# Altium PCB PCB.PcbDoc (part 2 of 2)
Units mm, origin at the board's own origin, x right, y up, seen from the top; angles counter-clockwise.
Board outline 41 x 25.36 mm, 4 copper layers (TOP, GND, SIG, BOTTOM), stack 1.586 mm thick; 138 components, 30 nets, 293 pads, 110 vias.
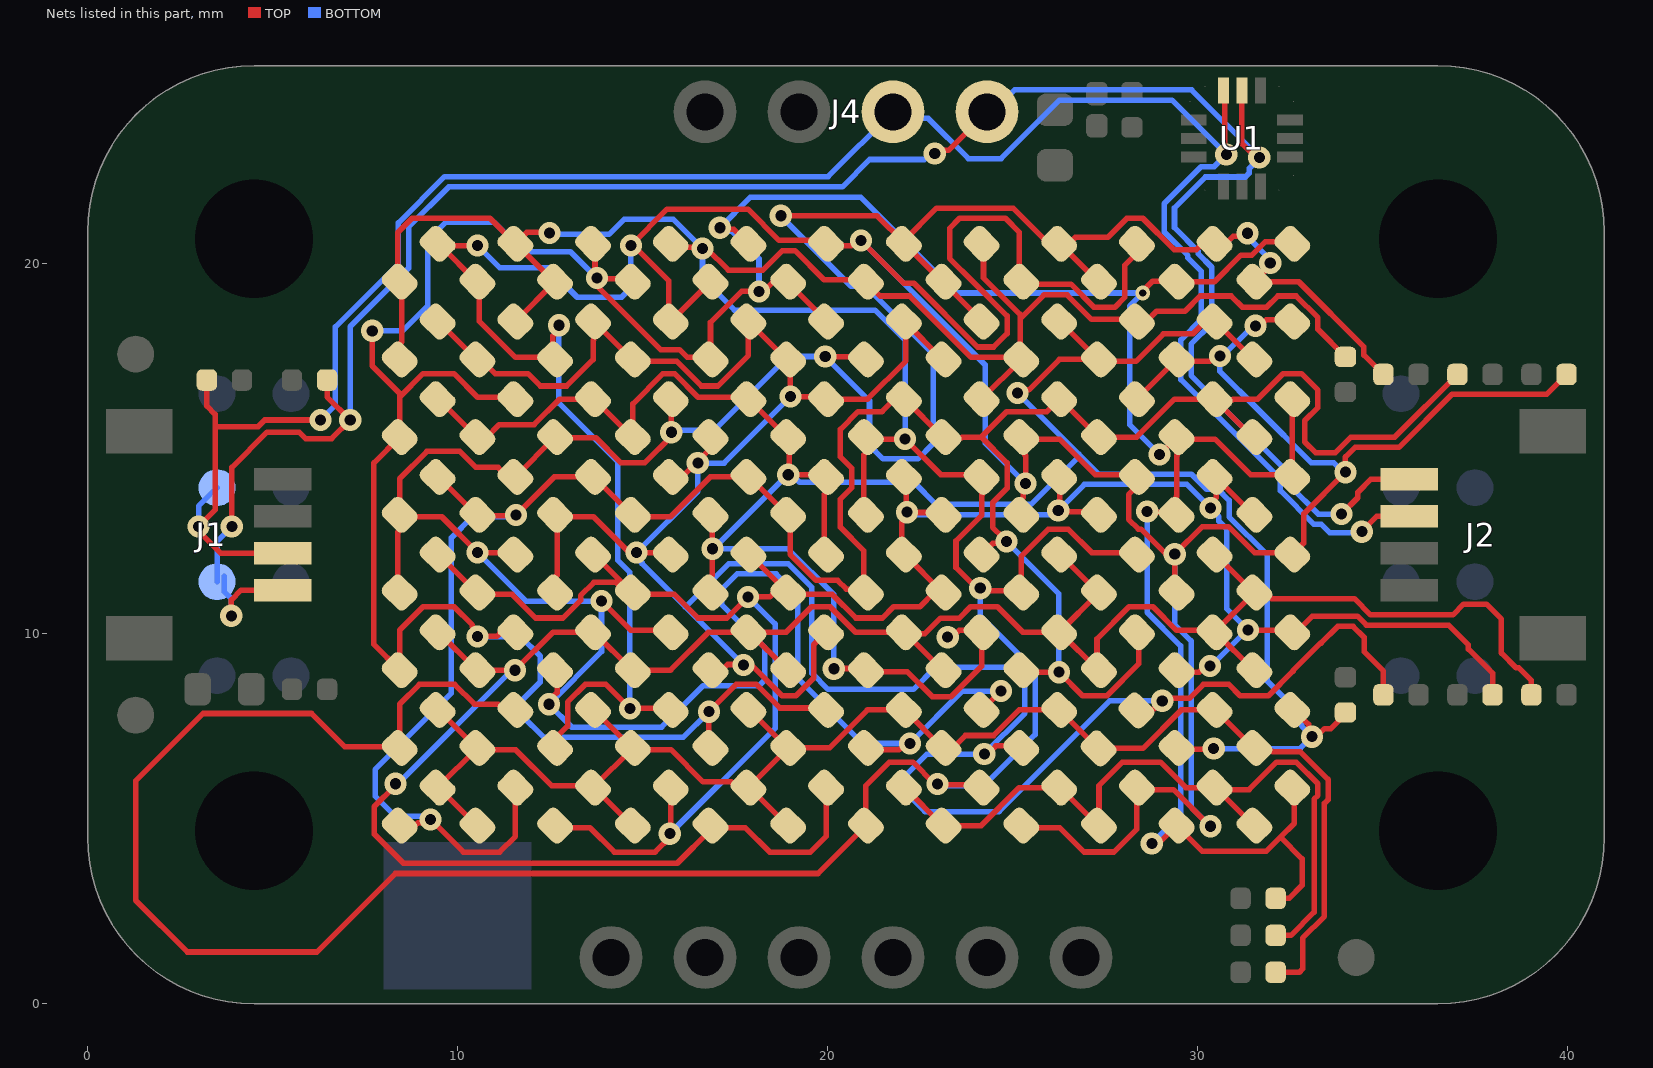
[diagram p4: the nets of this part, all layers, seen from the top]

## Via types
v1: diameter 0.6, hole 0.3, TOP to BOTTOM, tented both sides, 108 vias
v2: diameter 0.4, hole 0.2, TOP to BOTTOM, tented both sides, 2 vias

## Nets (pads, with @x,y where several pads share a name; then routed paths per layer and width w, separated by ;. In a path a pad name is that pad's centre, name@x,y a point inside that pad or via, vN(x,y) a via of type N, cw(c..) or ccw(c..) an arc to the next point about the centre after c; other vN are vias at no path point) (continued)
ROW0_3: 1.A 2.C 3.A 4.C 7.A 8.C 13.A 14.C 21.A 22.C 31.A 32.C 43.A 44.C 57.A 58.C 73.A 74.C 91.A 92.C R34.1 | length 118.3
  TOP w0.15: 13.A@8.438,17.417 8.425,17.43 8.425,17.822 8.491,17.887 8.491,19.464 1.A@8.438,19.517 8.385,19.57 8.385,20.846 8.771,21.232 10.874,21.232 2.C@11.563,20.542 ; 74.C@11.563,7.942 11.252,7.942 11.095,8.099 10.455,8.099 9.922,8.632 8.971,8.632 8.438,8.099 8.438,7.334 8.425,7.322 8.425,6.93 73.A@8.438,6.917 8.403,6.952 6.948,6.952 6.053,7.847 3.123,7.847 1.3,6.024 1.3,2.8 2.7,1.4 6.2,1.4 8.322,3.522 19.743,3.522 91.A@21.038,4.817 21.025,4.83 21.025,5.222 21.038,5.234 21.038,5.899 21.671,6.532 22.305,6.532 22.897,5.94 v1(22.97,5.94) ; 14.C@11.563,18.442 3.A@12.638,19.517 12.613,19.517 11.588,20.542 2.C@11.563,20.542 ; v1(12.486,20.833) 12.469,20.85 11.871,20.85 2.C@11.563,20.542 ; 4.C@15.763,20.542 15.852,20.454 16.588,20.454 v1(16.623,20.418) 16.731,20.418 17.32,19.83 18.252,19.83 18.781,20.358 19.122,20.358 19.91,19.57 20.985,19.57 7.A@21.038,19.517 21.423,19.132 22.218,19.132 23.88,17.47 25.185,17.47 21.A@25.204,17.451 ; 43.A@21.038,13.217 20.985,13.27 20.985,14.846 21.051,14.912 31.A@21.051,15.304 ; 31.A@21.038,15.317 31.A@21.051,15.304 ; v1@22.992,5.918 24.088,5.918 92.C@24.163,5.842 ; v1@24.08,11.185 23.474,11.792 23.474,12.51 24.163,13.2 24.163,13.742 24.176,13.755 44.C@24.176,14.229 ; v1(24.129,11.234) 24.095,11.201 24.095,11.17 25.185,11.17 57.A@25.225,11.13 ; 44.C@24.163,14.242 24.106,14.299 23.063,14.299 v1(22.098,15.264) 21.091,15.264 31.A@21.051,15.304 ; 32.C@24.163,16.342 21.A@25.238,17.417 21.A@25.204,17.451 ; 8.C@24.163,20.542 24.216,20.489 24.216,19.623 25.204,18.635 25.204,18.512 ; 57.A@25.238,11.117 57.A@25.225,11.13 ; 58.C@28.363,12.142 28.31,12.195 27.142,12.195 26.505,12.832 25.971,12.832 25.238,12.099 25.238,11.534 25.225,11.522 57.A@25.225,11.13 ; R34.1@34,17.485 33.253,18.232 33.253,18.547 32.668,19.132 32.171,19.132 31.866,18.827 31.211,18.827 30.907,19.132 30.071,19.132 29.658,18.719 28.895,18.719 28.618,18.442 22.C@28.363,18.442 28.306,18.499 27.138,18.499 26.477,19.16 25.852,19.16 25.204,18.512 ; 21.A@25.204,17.451 25.204,18.333 25.204,18.512
  BOTTOM w0.15: v1@12.484,20.83 12.52,20.795 14.095,20.795 14.504,21.204 15.833,21.204 16.621,20.416 16.621,19.612 17.481,18.751 21.281,18.751 22.096,17.937 v1@22.096,15.261 ; v1@22.967,5.938 23.008,5.897 24.236,5.897 25.613,7.274 25.613,9.011 24.126,10.498 v1@24.126,11.232
ROW1_3: 1.C 2.A 5.A 6.C 9.A 10.C 15.A 16.C 23.A 24.C 33.A 34.C 45.A 46.C 59.A 60.C 75.A 76.C 93.A 94.C R30.1 | length 113.7
  TOP w0.15: 1.C@9.463,20.542 9.511,20.494 1.C@9.536,20.494 ; v1(10.538,20.499) 10.533,20.494 1.C@9.536,20.494 ; 15.A@12.585,17.47 11.567,17.47 10.591,18.446 10.591,19.464 2.A@10.538,19.517 10.513,19.517 1.C@9.536,20.494 ; 75.A@12.638,6.917 12.638,7.171 12.974,7.507 12.974,8.153 13.452,8.632 14.01,8.632 v1(14.66,7.982) 14.667,7.989 15.717,7.989 76.C@15.763,7.942 ; 15.A@12.638,17.417 12.579,17.476 12.579,18.057 12.741,18.218 v1(12.741,18.34) ; 5.A@16.838,19.517 16.C@15.763,18.442 15.71,18.495 15.71,19.541 14.751,20.5 v1(14.685,20.5) 15.663,21.478 17.849,21.478 18.692,20.635 19.87,20.635 6.C@19.963,20.542 20.016,20.489 v1@20.643,20.489 ; v1(20.906,20.63) 22.055,19.48 22.331,19.48 24.058,17.753 24.492,17.753 24.853,18.114 24.853,18.595 23.939,19.508 23.939,19.51 23.3,20.149 23.3,20.961 23.571,21.232 24.805,21.232 25.185,20.852 25.185,19.57 9.A@25.238,19.517 25.302,19.453 26.576,19.453 27.202,18.827 27.766,18.827 28.032,19.093 28.032,19.957 28.363,20.288 10.C@28.363,20.542 ; 93.A@25.238,4.817 25.291,4.764 26.273,4.764 26.934,4.103 27.742,4.103 28.363,4.724 28.363,5.425 28.376,5.438 94.C@28.376,5.829 ; 45.A@25.238,13.217 25.225,13.23 25.225,13.622 25.292,13.688 25.292,14 v1(25.355,14.063) 25.355,14.816 25.331,14.84 25.331,15.224 33.A@25.291,15.264 ; 33.A@25.238,15.317 33.A@25.291,15.264 ; 94.C@28.363,5.842 94.C@28.376,5.829 ; 34.C@28.363,16.342 23.A@29.438,17.417 29.491,17.364 30.339,17.364 30.485,17.51 v1(30.606,17.51) ; 59.A@29.438,11.117 29.385,11.17 v1(29.385,12.152) ; v1(30.351,4.8) 30.337,4.8 29.348,5.789 28.416,5.789 94.C@28.376,5.829 ; v1(31.571,18.325) 31.693,18.325 31.863,18.495 32.51,18.495 24.C@32.563,18.442 ; R30.1@39.975,17.01 39.445,16.48 36.887,16.48 35.447,15.04 34.26,15.04 34,14.78 v1(34,14.369) 32.873,13.241 32.873,12.452 60.C@32.563,12.142 32.51,12.195 31.542,12.195 30.838,12.899 30.132,12.899 v1(29.385,12.152) ; 33.A@25.291,15.264 26.273,15.264 27.242,14.295 28.31,14.295 46.C@28.363,14.242 28.363,13.988 28.138,13.762 28.138,13.096 28.402,12.832 28.468,12.832 29.148,12.152 v1(29.385,12.152)
  BOTTOM w0.15: v1@10.536,20.497 11.136,19.897 12.436,19.897 13.236,19.097 14.436,19.097 14.682,19.343 v1@14.682,20.497 ; v1(12.741,18.34) 12.741,16.239 14.334,14.646 14.334,11.985 14.657,11.661 v1@14.657,7.979 ; v1@20.903,20.627 24.258,17.272 24.258,15.155 v1@25.352,14.061 ; v1@29.382,12.15 29.382,10.25 29.826,9.806 29.826,5.32 v1@30.349,4.797 ; v1(31.571,18.325) 31.497,18.325 30.681,17.51 v1(30.606,17.51) 30.606,17.094 31.616,16.084 33.079,14.621 33.687,14.621 33.939,14.369 v1(34,14.369)
ROW2_3: 3.C 4.A 5.C 6.A 11.A 12.C 17.A 18.C 25.A 26.C 35.A 36.C 47.A 48.C 61.A 62.C 77.A 78.C 95.A 96.C R31.1 | length 105.3
  TOP w0.15: v1(7.696,18.19) 7.696,17.241 8.438,16.499 8.438,16.399 ; 61.A@8.438,9.017 61.A@8.425,9.029 ; 62.C@11.563,10.042 11.176,10.042 11.063,9.929 v1(10.541,9.929) 10.541,10.051 10.403,10.188 10.403,10.234 9.906,10.731 9.071,10.731 8.438,10.098 8.438,9.434 8.425,9.421 61.A@8.425,9.029 ; 26.C@11.563,16.342 11.51,16.395 10.542,16.395 9.905,17.032 9.071,17.032 8.438,16.399 ; 3.C@13.663,20.542 13.716,20.489 v1@13.716,19.718 ; v1@13.716,19.615 13.716,19.458 15.49,17.684 16,17.684 16.214,17.47 16.785,17.47 17.A@16.825,17.43 ; v1@13.788,19.592 14.662,19.592 4.A@14.738,19.517 ; 77.A@16.838,6.917 16.795,6.96 v1(16.795,7.896) 17.53,8.632 18.079,8.632 18.715,7.995 19.91,7.995 78.C@19.963,7.942 ; 17.A@16.838,17.417 17.A@16.825,17.43 ; v1(17.089,20.976) 17.125,20.941 17.464,20.941 5.C@17.863,20.542 ; 18.C@19.963,18.442 19.963,18.467 18.938,19.492 6.A@18.938,19.517 18.932,19.523 18.54,19.523 18.273,19.255 v1(18.151,19.255) 17.677,19.255 16.838,18.417 16.838,17.834 16.825,17.822 17.A@16.825,17.43 ; v2(28.521,19.212) 28.521,19.261 28.79,19.53 29.425,19.53 29.451,19.504 29.842,19.504 29.855,19.517 30.456,19.517 31.177,20.238 31.471,20.238 31.829,20.595 32.51,20.595 12.C@32.563,20.542 ; v1(28.64,13.304) 28.657,13.287 29.368,13.287 47.A@29.425,13.23 ; v1@28.844,4.223 95.A@29.438,4.817 30.127,4.127 31.865,4.127 32.24,4.503 ; v1(28.971,14.85) 35.A@29.438,15.317 35.A@29.451,15.304 ; 47.A@29.438,13.217 47.A@29.425,13.23 ; R31.1@32.115,2.85 32.474,2.85 32.829,3.204 32.829,3.915 32.24,4.503 ; 96.C@32.563,5.842 32.616,5.789 32.616,4.879 32.24,4.503 ; 36.C@32.563,16.342 32.563,14.348 32.51,14.295 31.442,14.295 30.473,15.264 29.491,15.264 35.A@29.451,15.304 ; 61.A@8.425,9.029 7.738,9.716 7.738,14.617 25.A@8.438,15.317 8.425,15.33 8.425,15.722 8.438,15.734 8.438,16.399 ; 47.A@29.425,13.23 29.425,13.705 29.438,13.717 29.438,14.816 29.451,14.829 35.A@29.451,15.304
  BOTTOM w0.15: v1(7.696,18.19) 8.51,18.19 9.2,18.88 9.2,20.642 9.685,21.127 10.982,21.127 11.781,20.328 13.048,20.328 v1@13.764,19.612 ; v1@10.538,9.926 11.706,9.926 12.236,9.397 12.236,8.697 11.736,8.197 11.736,7.797 12.332,7.2 16.099,7.2 v1@16.792,7.894 ; v1@17.087,20.974 17.173,20.888 17.405,20.888 18.149,20.143 v1@18.149,19.253 ; v1(17.089,20.976) 17.916,21.803 20.897,21.803 23.488,19.212 v2(28.521,19.212) 28.517,19.212 28.165,18.86 28.165,15.656 v1(28.971,14.85) ; v1@28.636,4.206 29.547,5.117 29.547,7.98 29.549,7.982 29.549,8.398 29.547,8.4 29.547,9.673 28.636,10.583 v1@28.636,13.3
  other v1: 28.766,4.336 13.766,19.615
ROW3_3: 7.C 8.A 9.C 10.A 11.C 12.A 19.A 20.C 27.A 28.C 37.A 38.C 49.A 50.C 63.A 64.C 79.A 80.C R4.1 | length 94.6
  TOP w0.15: 49.A@8.438,11.117 8.385,11.17 8.385,12.746 8.451,12.812 37.A@8.451,13.204 ; 50.C@11.563,12.142 11.51,12.195 10.542,12.195 v1(10.538,12.199) 9.573,13.164 8.491,13.164 37.A@8.451,13.204 ; v1(12.472,8.098) 12.472,8.189 12.691,8.409 12.691,8.964 63.A@12.638,9.017 ; v1(13.893,10.887) 14.685,10.095 15.71,10.095 64.C@15.763,10.042 ; 28.C@15.763,16.342 15.779,16.326 15.779,15.34 15.066,14.627 14.41,14.627 13.738,15.299 12.656,15.299 27.A@12.638,15.317 38.C@11.563,14.242 11.356,14.242 11.099,14.499 10.495,14.499 10.063,14.932 9.171,14.932 8.438,14.199 8.438,13.634 8.425,13.622 8.425,13.23 37.A@8.438,13.217 37.A@8.451,13.204 ; v1(18.738,21.299) 21.338,21.299 7.C@22.063,20.574 ; v1(19.938,17.499) 19.953,17.485 20.97,17.485 19.A@21.038,17.417 ; 79.A@21.038,6.917 21.091,6.864 21.931,6.864 22.105,7.038 v1(22.227,7.038) ; 80.C@24.163,7.942 24.181,7.942 v1(24.69,8.451) ; 20.C@24.163,18.442 24.163,18.467 23.138,19.492 23.113,19.492 23.113,19.517 22.088,20.542 7.C@22.063,20.542 7.C@22.063,20.574 ; 9.C@26.341,20.489 27.313,19.517 10.A@27.338,19.517 ; 11.C@30.463,20.542 30.125,20.542 29.969,20.386 29.367,20.386 28.521,21.232 28.093,21.232 27.58,20.719 26.702,20.719 26.526,20.542 26.341,20.542 25.986,20.542 25.02,21.509 22.948,21.509 22.063,20.624 7.C@22.063,20.574 ; 11.C@30.823,20.548 30.823,20.6 30.965,20.742 31.265,20.742 v1(31.351,20.828) ; 12.A@31.591,19.464 12.A@31.538,19.517 ; v1(31.966,20.022) 31.866,19.922 31.866,19.845 12.A@31.538,19.517 ; R4.1@35.025,17.01 34.5,17.535 34.5,17.754 32.737,19.517 12.A@31.538,19.517
  BOTTOM w0.15: v1@10.536,12.197 11.848,10.884 13.891,10.884 13.891,9.517 12.469,8.095 13.087,7.477 15.516,7.477 16.636,8.597 18.148,8.597 18.305,8.753 18.305,9.628 17.136,10.797 17.136,11.197 17.559,11.62 18.613,11.62 19.197,11.035 19.197,8.79 20.951,7.035 22.225,7.035 23.638,8.449 v1@24.688,8.449 ; v1@15.776,15.445 15.828,15.497 16.936,15.497 18.936,17.497 19.936,17.497 21.136,16.297 21.136,15.097 21.505,14.728 22.445,14.728 22.858,15.142 22.858,17.57 21.038,19.39 20.642,19.39 v1@18.736,21.297 ; v1(31.351,20.828) 31.351,20.732 31.966,20.118 v1(31.966,20.022)
  other v1: 15.779,15.447
ROW4_3: 13.C 14.A 15.C 16.A 17.C 18.A 19.C 20.A 29.A 30.C 39.A 40.C 51.A 52.C 65.A 66.C 81.A 82.C R27.1 | length 80.6
  TOP w0.15: 13.C@9.463,18.442 9.488,18.442 10.513,17.417 10.629,17.417 11.014,17.032 11.905,17.032 12.238,16.699 12.949,16.699 13.663,17.413 13.663,17.942 13.676,17.955 15.C@13.676,18.429 ; 51.A@12.638,11.117 12.625,11.13 12.625,11.522 12.691,11.587 39.A@12.691,13.164 ; 39.A@12.638,13.217 39.A@12.691,13.164 ; 15.C@13.688,18.442 14.713,17.417 16.A@14.738,17.417 14.793,17.362 15.93,17.362 16.593,16.699 17.038,16.699 17.863,17.524 17.863,18.025 17.876,18.038 17.C@17.876,18.429 ; 52.C@15.763,12.142 15.71,12.195 v1(14.838,12.195) 14.642,12.195 13.673,13.164 39.A@12.691,13.164 ; 40.C@15.763,14.242 16.07,14.242 16.46,14.633 v1@16.512,14.633 ; v1(16.495,14.616) 16.495,14.668 16.838,15.011 29.A@16.838,15.317 ; 65.A@16.838,9.017 17.145,9.017 17.299,9.171 v1@17.733,9.171 ; 17.C@17.863,18.442 17.C@17.876,18.429 ; v1@17.932,9.171 18.775,8.327 19.149,8.327 19.627,8.806 19.627,9.707 66.C@19.963,10.042 ; 18.A@18.913,17.392 17.C@17.876,18.429 ; 18.A@18.938,17.417 18.996,17.358 18.996,16.417 v1(19.002,16.412) 19.01,16.403 19.902,16.403 30.C@19.963,16.342 19.976,16.329 20.368,16.329 20.381,16.342 21.081,16.342 22.116,17.377 22.116,18.389 19.C@22.063,18.442 22.088,18.442 23.113,17.417 20.A@23.138,17.417 ; v1(24.238,6.751) 24.33,6.751 24.549,6.97 25.185,6.97 81.A@25.238,6.917 ; 82.C@28.351,7.93 28.404,7.877 28.715,7.877 28.814,7.975 28.833,7.975 v1(29.047,8.19) 29.112,8.254 29.782,8.254 30.159,8.632 30.848,8.632 31.153,8.327 31.917,8.327 32.583,8.993 32.583,9.011 33.323,9.75 33.34,9.75 33.792,10.202 34.208,10.202 34.502,9.908 34.502,9.518 35.025,8.994 R27.1@35.025,8.35
  BOTTOM w0.15: 16.162,10.723 v1@17.731,9.153 ; v1@18.999,16.409 17.204,14.614 16.493,14.614 16.493,13.85 14.836,12.193 14.836,12.071 14.987,11.92 14.987,11.901 16.164,10.725 17.336,11.897 18.936,11.897 19.575,11.257 19.575,8.936 20.015,8.497 22.32,8.497 22.92,9.097 25.136,9.097 25.336,8.897 25.336,7.848 24.236,6.748 22.687,6.748 22.136,6.197 22.136,5.697 22.636,5.197 24.636,5.197 27.627,8.187 v1@29.045,8.187
  other v1: 17.733,9.156
ROW5_3: 21.C 22.A 23.C 24.A 25.C 26.A 27.C 28.A 29.C 30.A 41.A 42.C 53.A 54.C 67.A 68.C 83.A 84.C R33.1 | length 72.5
  TOP w0.15: 25.C@9.463,16.342 9.488,16.342 10.513,15.317 26.A@10.538,15.317 10.792,15.317 11.128,15.653 12.073,15.653 12.762,16.342 27.C@13.663,16.342 13.688,16.342 28.A@14.713,15.317 ; 28.A@14.725,15.33 14.725,15.722 14.738,15.734 14.738,16.218 15.552,17.032 15.868,17.032 16.505,16.395 17.81,16.395 29.C@17.863,16.342 30.A@18.913,15.292 ; 53.A@16.838,11.117 16.825,11.13 16.825,11.522 16.891,11.587 v1(16.891,12.299) 16.891,13.164 41.A@16.838,13.217 ; 30.A@18.938,15.317 18.965,15.29 18.965,14.325 v1(18.938,14.299) 18.94,14.297 19.908,14.297 42.C@19.963,14.242 ; 54.C@19.963,12.142 19.91,12.195 19.91,13.772 19.976,13.838 42.C@19.976,14.229 ; v1(20.17,9.056) 20.177,9.063 20.992,9.063 67.A@21.038,9.017 21.084,8.971 22.161,8.971 22.833,8.299 23.338,8.299 24.163,9.124 24.163,9.625 24.176,9.638 24.176,10.029 68.C@24.163,10.042 24.11,10.095 23.556,10.095 23.37,9.909 v1(23.248,9.909) ; v1(25.138,16.509) 25.224,16.595 25.446,16.595 26.268,17.417 26.92,17.417 26.933,17.43 22.A@27.3,17.43 ; 21.C@26.263,18.442 26.288,18.442 22.A@27.3,17.43 ; 83.A@29.438,6.917 29.473,6.881 30.421,6.881 v1(30.438,6.899) ; 24.A@31.591,17.364 24.A@31.538,17.417 31.513,17.417 30.488,18.442 23.C@30.463,18.442 30.209,18.442 29.873,18.107 29.077,18.107 28.335,17.364 27.391,17.364 22.A@27.338,17.417 27.325,17.43 22.A@27.3,17.43 ; 84.C@32.563,7.942 32.615,7.942 33.006,7.551 33.006,7.306 v1(33.092,7.22) 33.214,7.22 33.434,7.439 33.604,7.439 R33.1@34.04,7.875
  BOTTOM w0.15: v1@20.168,9.053 20.168,11.064 18.936,12.297 16.912,12.297 18.912,14.297 19.049,14.297 19.249,14.097 22.336,14.097 22.936,13.497 25.498,13.497 26.8,14.799 26.8,14.847 ; v1(25.138,16.509) 26.8,14.847 ; v1(30.438,6.899) 32.772,6.899 v1(33.092,7.22) 33.092,7.234 32.817,7.51 32.817,7.793 31.89,8.719 31.89,12.128 30.855,13.163 30.855,13.609 30.561,13.903 30.248,13.903 29.832,14.318 27.328,14.318 26.8,14.847
ROW6_3: 31.C 32.A 33.C 34.A 35.C 36.A 37.C 38.A 39.C 40.A 41.C 42.A 55.A 56.C 69.A 70.C 85.A 86.C R32.1 | length 73.5
  TOP w0.15: 85.A@8.438,4.817 8.451,4.804 8.842,4.804 8.932,4.894 9.183,4.894 v1@9.269,4.98 ; v1@9.278,4.98 10.159,4.099 11.138,4.099 11.563,4.524 11.563,5.425 11.576,5.438 11.576,5.829 86.C@11.563,5.842 ; 37.C@9.463,14.242 9.488,14.242 10.513,13.217 38.A@10.538,13.217 10.565,13.189 v1@11.553,13.189 ; v1@11.587,13.215 12.614,14.242 13.246,14.242 13.259,14.255 13.65,14.255 39.C@13.663,14.242 13.688,14.242 14.713,13.217 40.A@14.738,13.217 14.791,13.164 15.753,13.164 16.831,14.242 17.446,14.242 17.459,14.255 17.85,14.255 41.C@17.863,14.242 17.888,14.242 18.913,13.217 42.A@18.938,13.217 18.991,13.164 18.991,12.146 19.695,11.443 20.275,11.443 20.508,11.21 20.945,11.21 55.A@20.985,11.17 ; 55.A@21.038,11.117 55.A@20.985,11.17 ; 56.C@24.163,12.397 56.C@24.163,12.142 24.47,12.449 24.788,12.449 v1(24.838,12.499) ; v1@24.738,12.599 24.461,12.876 24.461,13.543 24.853,13.935 24.853,14.62 24.156,15.317 ; 69.A@25.238,9.017 25.291,8.964 v1(26.257,8.964) 26.894,8.327 27.549,8.327 28.416,9.194 28.416,9.989 70.C@28.363,10.042 ; 35.C@30.463,16.342 35.C@30.476,16.329 ; 35.C@30.463,16.355 30.059,16.355 30.046,16.342 29.381,16.342 28.356,15.317 27.755,15.317 27.742,15.304 27.351,15.304 34.A@27.338,15.317 27.313,15.317 26.288,16.342 33.C@26.263,16.342 25.927,16.007 24.846,16.007 24.156,15.317 ; 36.A@31.538,15.317 31.488,15.317 35.C@30.476,16.329 ; R32.1@37.025,17.01 35.332,15.317 34.145,15.317 33.726,14.898 33.192,14.898 32.898,15.192 32.898,15.759 33.253,16.114 33.253,16.589 32.81,17.032 32.318,17.032 31.628,16.342 30.964,16.342 30.951,16.329 35.C@30.476,16.329 ; 55.A@20.985,11.17 20.985,12.244 20.348,12.88 20.348,13.643 20.653,13.947 20.653,14.478 20.348,14.783 20.348,15.528 20.827,16.007 21.473,16.007 21.809,16.342 31.C@22.063,16.342 22.088,16.342 23.113,15.317 32.A@23.138,15.317 23.151,15.304 23.625,15.304 23.638,15.317 24.156,15.317
  BOTTOM w0.15: v1(9.27,4.98) 9.183,5.066 8.965,5.066 8.957,5.075 8.31,5.075 7.771,5.614 7.771,6.332 9.836,8.397 9.836,12.597 10.407,13.168 11.531,13.168 v1@11.576,13.213 ; v1@24.836,12.497 26.255,11.077 v1@26.255,8.961
  other v1: 11.579,13.215
ROW7_3: 43.C 44.A 45.C 46.A 47.C 48.A 49.C 50.A 51.C 52.A 53.C 54.A 55.C 56.A 71.A 72.C 87.A 88.C R28.1 | length 64
  TOP w0.15: 49.C@9.463,12.142 9.488,12.142 10.513,11.117 50.A@10.538,11.117 10.591,11.064 11.473,11.064 12.11,10.427 12.849,10.427 13.327,10.906 13.327,11.031 13.685,11.389 14.288,11.389 14.56,11.117 52.A@14.738,11.117 14.791,11.064 15.862,11.064 16.499,10.427 17.282,10.427 v1(17.853,10.999) 18.441,10.999 18.558,11.117 54.A@18.913,11.117 ; 87.A@12.638,4.817 12.691,4.764 13.573,4.764 14.238,4.099 15.338,4.099 v1@15.763,4.524 ; 51.C@13.663,12.142 13.688,12.142 52.A@14.7,11.13 ; v1@15.763,4.599 15.763,5.425 15.776,5.438 15.776,5.829 88.C@15.763,5.842 ; 53.C@17.863,12.142 17.888,12.142 54.A@18.913,11.117 ; 43.C@22.063,14.242 22.133,14.173 22.133,13.305 v1(22.149,13.288) ; 56.A@23.138,11.117 56.A@23.113,11.117 ; 44.A@23.138,13.217 23.076,13.279 22.158,13.279 v1(22.149,13.288) ; 45.C@26.263,14.242 26.277,14.228 26.277,13.373 v1(26.238,13.334) 26.27,13.302 27.253,13.302 46.A@27.338,13.217 ; 71.A@29.438,9.017 29.491,8.964 30.046,8.964 30.216,9.134 v1(30.338,9.134) ; v1(30.353,13.401) 30.353,13.523 30.51,13.68 30.51,14.161 30.527,14.178 47.C@30.463,14.242 ; 47.C@30.54,14.191 31.513,13.217 48.A@31.538,13.217 ; v1(31.367,10.105) 31.371,10.1 32.505,10.1 32.616,9.989 33.106,10.479 34.323,10.479 34.566,10.236 36.79,10.236 37.323,9.703 37.323,9.588 37.975,8.936 R28.1@37.975,8.35 ; 54.A@18.913,11.117 54.A@18.938,11.117 18.991,11.064 20.128,11.064 20.765,10.427 21.482,10.427 21.786,10.732 22.498,10.732 22.883,11.117 56.A@23.113,11.117 ; v1(22.149,13.288) 22.149,13.167 22.01,13.027 22.01,12.195 55.C@22.063,12.142 22.088,12.142 56.A@23.113,11.117
  BOTTOM w0.15: v1@15.736,4.597 18.582,7.443 18.582,10.266 v1@17.851,10.997 ; v1@22.147,13.286 22.213,13.22 26.002,13.22 26.064,13.282 26.186,13.282 26.946,14.041 29.713,14.041 30.35,13.404 30.35,13.399 30.578,13.171 30.578,13.049 30.786,12.841 30.786,10.681 31.364,10.102 31.341,10.102 30.37,9.131 v1@30.336,9.131
  other v1: 15.738,4.599
ROW8_3: 57.C 58.A 59.C 60.A 61.C 62.A 63.C 64.A 65.C 66.A 67.C 68.A 69.C 70.A 71.C 72.A 89.A 90.C R29.1 | length 66.9
  TOP w0.15: v1(8.321,5.948) 8.321,5.906 7.748,5.333 7.748,4.589 8.538,3.799 15.938,3.799 16.838,4.699 89.A@16.838,4.817 16.891,4.764 17.773,4.764 18.438,4.099 19.538,4.099 19.963,4.524 19.963,5.425 19.976,5.438 19.976,5.829 90.C@19.963,5.842 ; 61.C@9.463,10.042 9.488,10.042 10.513,9.017 62.A@10.538,9.017 10.551,9.004 10.942,9.004 10.955,9.017 v1(11.556,9.017) 12.581,10.042 13.246,10.042 13.259,10.055 13.65,10.055 63.C@13.663,10.042 13.688,10.042 14.713,9.017 64.A@14.738,9.017 14.751,9.004 15.142,9.004 15.155,9.017 15.756,9.017 16.781,10.042 17.446,10.042 17.459,10.055 17.85,10.055 65.C@17.863,10.042 17.876,10.029 65.C@17.901,10.029 ; 66.A@18.938,9.017 18.913,9.017 65.C@17.901,10.029 ; 68.A@23.138,9.017 23.113,9.017 67.C@22.133,9.997 ; 57.C@26.263,12.142 26.288,12.142 27.313,11.117 58.A@27.338,11.117 69.C@26.263,10.042 ; 59.C@30.463,12.142 30.488,12.142 31.513,11.117 60.A@31.538,11.117 ; 72.A@31.538,9.017 31.513,9.017 30.488,10.042 71.C@30.463,10.042 ; R29.1@39.025,8.35 39.025,8.74 38.687,9.078 38.617,9.078 38.212,9.482 38.212,10.398 37.808,10.802 37.194,10.802 36.905,10.513 34.68,10.513 34.239,10.954 32.012,10.954 31.849,11.117 60.A@31.538,11.117 ; 65.C@17.901,10.029 18.268,10.029 18.281,10.042 18.881,10.042 19.571,10.732 20.068,10.732 20.758,10.042 21.646,10.042 21.659,10.055 22.05,10.055 67.C@22.063,10.042 22.109,9.997 67.C@22.133,9.997 ; 67.C@22.133,9.997 22.626,9.997 23.054,10.424 23.563,10.424 23.871,10.732 24.592,10.732 25.281,10.042 25.846,10.042 25.859,10.055 26.25,10.055 69.C@26.263,10.042 ; 69.C@26.263,10.042 26.288,10.042 27.313,9.017 70.A@27.338,9.017 27.285,9.07 27.285,9.865 28.152,10.732 28.798,10.732 29.434,10.095 30.41,10.095 71.C@30.463,10.042 ; 71.C@30.463,10.042 60.A@31.538,11.117
  BOTTOM w0.15: v1@8.319,5.946 8.385,5.946 11.454,9.014 v1@11.554,9.014
ROW9_3: 73.C 74.A 75.C 76.A 77.C 78.A 79.C 80.A 81.C 82.A 83.C 84.A 85.C 86.A 87.C 88.A 89.C 90.A R16.1 | length 44.4
  TOP w0.15: 73.C@9.463,7.942 9.488,7.942 10.513,6.917 74.A@10.538,6.917 ; 86.A@10.538,4.817 10.513,4.817 9.488,5.842 85.C@9.463,5.842 74.A@10.538,6.917 ; 75.C@13.663,7.942 13.688,7.942 14.713,6.917 76.A@14.738,6.917 ; 88.A@14.738,4.817 14.713,4.817 13.688,5.842 87.C@13.663,5.842 ; 77.C@17.863,7.942 17.888,7.942 18.913,6.917 78.A@18.938,6.917 ; 90.A@18.938,4.817 18.913,4.817 17.888,5.842 89.C@17.863,5.842 ; R16.1@32.115,0.85 32.75,0.85 32.842,0.942 32.842,1.776 33.43,2.363 33.43,5.416 33.53,5.516 33.53,6.062 32.783,6.809 32.038,6.809 32.023,6.824 31.631,6.824 84.A@31.538,6.917 31.513,6.917 30.488,7.942 83.C@30.463,7.942 30.45,7.955 30.059,7.955 30.046,7.942 29.562,7.942 28.525,6.905 27.743,6.905 27.73,6.892 27.338,6.892 82.A@27.326,6.905 27.313,6.905 26.276,7.942 81.C@26.263,7.942 26.25,7.955 25.859,7.955 25.846,7.942 25.181,7.942 24.492,7.253 23.728,7.253 23.392,6.917 23.113,6.917 22.088,7.942 79.C@22.063,7.942 22.05,7.955 21.659,7.955 21.646,7.942 21.081,7.942 20.056,6.917 19.355,6.917 19.342,6.904 18.951,6.904 78.A@18.938,6.917 ; 74.A@10.538,6.917 10.591,6.864 11.573,6.864 12.542,5.895 13.61,5.895 87.C@13.663,5.842 ; 87.C@13.663,5.842 76.A@14.738,6.917 ; 76.A@14.738,6.917 14.784,6.871 15.766,6.871 16.638,5.999 17.395,5.999 17.552,5.842 89.C@17.863,5.842 ; 89.C@17.863,5.842 78.A@18.938,6.917
ROW10_3: 91.C 92.A 93.C 94.A 95.C 96.A R14.1 | length 20.9
  TOP w0.15: 91.C@22.063,5.842 22.088,5.842 23.113,4.817 92.A@23.138,4.817 23.151,4.804 23.542,4.804 23.555,4.817 24.156,4.817 25.181,5.842 25.846,5.842 25.859,5.855 26.25,5.855 93.C@26.263,5.842 26.288,5.842 27.3,4.83 27.325,4.83 27.325,5.222 27.338,5.234 27.338,5.899 27.971,6.532 28.997,6.532 29.687,5.842 30.046,5.842 30.059,5.855 30.45,5.855 30.516,5.789 95.C@30.541,5.789 ; 96.A@31.538,4.817 31.513,4.817 95.C@30.541,5.789 ; R14.1@32.115,1.85 32.525,1.85 33.153,2.478 33.153,5.531 33.253,5.631 33.253,5.947 32.668,6.532 32.139,6.532 31.397,5.789 95.C@30.541,5.789
SCL_1: J1.4 J2.4 J4.4 R3.1 SCL.X U1.18 | length 60.9
  TOP w0.15: v1(3.886,10.486) 3.886,10.916 4.15,11.18 J1.4@5.275,11.18 ; v1(3.9,12.9) 3.9,14.498 4.854,15.453 5.718,15.453 5.892,15.278 6.598,15.278 v1(7.1,15.78) 6.475,16.405 R3.1@6.475,16.86 ; v1(22.9,22.98) 22.986,23.066 23.266,23.066 J4.4@24.31,24.11 ; U1.18@31.2,24.6 31.2,23.251 31.577,22.874 v1(31.671,22.874) ; v1(33.89,13.238) 34.331,13.678 34.331,13.825 34.686,14.18 J2.4@35.726,14.18
  BOTTOM w0.15: SCL.X@3.5,11.41 3.5,12.5 v1(3.9,12.9) ; SCL.X@3.694,11.557 3.694,11.14 3.886,10.948 v1(3.886,10.486) ; v1(7.1,15.78) 7.1,18.304 8.677,19.881 8.677,20.994 9.763,22.08 20.4,22.08 21.14,22.82 22.618,22.82 22.778,22.98 v1(22.9,22.98) ; J4.4@24.31,24.11 24.466,24.11 25.06,24.704 29.841,24.704 v1(31.671,22.874) 31.671,22.851 31.4,22.579 31.4,22.454 31.294,22.348 30.216,22.348 29.379,21.512 29.379,20.98 30.018,20.341 30.018,20.276 30.385,19.909 30.385,18.39 29.827,17.833 29.827,16.987 32.517,14.297 32.517,13.984 33.264,13.238 v1(33.89,13.238)
SDA_1: J1.3 J2.3 J4.3 R2.1 SDA.X U1.19 | length 60.3
  TOP w0.15: R2.1@3.225,16.86 3.225,16.155 3.448,15.932 3.448,15.598 3.448,13.348 v1(3,12.9) 3,12.778 3.186,12.592 3.598,12.18 J1.3@5.275,12.18 ; 3.448,15.634 3.484,15.598 4.608,15.598 4.79,15.78 v1(6.3,15.78) ; U1.19@30.7,24.6 30.74,24.56 30.74,22.998 v1(30.78,22.958) ; v1(34.442,12.761) 34.442,12.771 34.851,13.18 J2.3@35.726,13.18
  BOTTOM w0.15: v1(3,12.9) 3,13.45 SDA.X@3.5,13.95 ; v1(6.3,15.78) 6.7,16.18 6.7,18.295 8.4,19.995 8.4,21.108 9.649,22.357 20.017,22.357 J4.3@21.77,24.11 21.945,23.935 22.72,23.935 23.809,22.846 24.693,22.846 26.274,24.427 29.311,24.427 v1(30.78,22.958) 30.447,22.625 30.101,22.625 29.102,21.627 29.102,20.865 29.741,20.226 29.741,20.161 30.108,19.794 30.108,18.505 29.55,17.947 29.55,16.872 32.24,14.183 32.24,13.87 33.149,12.961 33.348,12.961 33.573,12.736 34.417,12.736 v1(34.442,12.761)
pads on no net: Fiducial_1.1 Fiducial_2.1 Fiducial_3.1 PA6.X PA7.X PC14.X PC15.X TP9.X TP10.X TP11.X TP12.X U1.1 U1.20

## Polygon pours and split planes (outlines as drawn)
GND on TOP "NONET_L04_P-001" (solid, remove dead copper, pour order 8): 0,4.5 ccw(c4.5,4.5) 4.5,0 36.5,0 ccw(c36.5,4.5) 41,4.5 41,20.86 ccw(c36.5,20.86) 36.5,25.36 4.5,25.36 ccw(c4.5,20.86) 0,20.86
GND on BOTTOM "NONET_L04_P-001" (solid, remove dead copper, pour order 9): 0,4.5 ccw(c4.5,4.5) 4.5,0 36.5,0 ccw(c36.5,4.5) 41,4.5 41,20.86 ccw(c36.5,20.86) 36.5,25.36 4.5,25.36 ccw(c4.5,20.86) 0,20.86
GND on GND "NONET_L04_P-001" (solid, remove dead copper, pour order 10): 0,4.5 ccw(c4.5,4.5) 4.5,0 36.5,0 ccw(c36.5,4.5) 41,4.5 41,20.86 ccw(c36.5,20.86) 36.5,25.36 4.5,25.36 ccw(c4.5,20.86) 0,20.86
+3V3 on SIG "NONET_L04_P-001" (solid, remove dead copper, pour order 11): 0,4.5 ccw(c4.5,4.5) 4.5,0 36.5,0 ccw(c36.5,4.5) 41,4.5 41,20.86 ccw(c36.5,20.86) 36.5,25.36 4.5,25.36 ccw(c4.5,20.86) 0,20.86

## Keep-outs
Keep-Out Layer:
  circle w0.05: c36.5,4.68 r2.75
  circle w0.05: c36.5,20.68 r2.75
  circle w0.05: c4.5,4.68 r2.75
  circle w0.05: c4.5,20.68 r2.75

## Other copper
BOTTOM:
  rectangle net GND: 7.6,0.3 12.4,4.099
  region: 421 vertices and 0 holes, not listed, extent 36.94,15.957 38.051,17.048

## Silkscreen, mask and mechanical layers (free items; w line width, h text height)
Route Tool Path:
  lines w2: -1,8.498 -1,16.86 ; 42,4.5 cw(c36.5,4.5) 36.5,-1 ; 42,8.498 42,16.86 ; -1,4.498 cw(c0,4.5) -1,4.5 ccw(c4.5,4.5) -1,4.498 ; -1,4.498 ccw(c4.5,4.5) 4.498,-1 ; -1,20.86 cw(c4.5,20.86) 4.5,26.36 ; -1,20.86 -1,20.86 ; 4.498,-1 ccw(c4.5,0) 4.5,-1 ; 4.498,-1 ccw(c4.5,4.5) 4.5,-1 ; 4.5,-1 36.5,-1 ; 4.5,26.36 4.5,26.36 ; 4.5,26.36 36.5,26.36 ; 36.5,-1 36.5,-1 ; 36.5,26.36 cw(c36.5,25.36) 36.502,26.36 ; 36.5,26.36 cw(c36.5,20.86) 36.502,26.36 ; 36.502,26.36 cw(c36.5,20.86) 42,20.863 ; 42,20.863 cw(c36.5,20.86) 42,20.86 ccw(c41,20.86) 42,20.863
Board:
  the board outline again, w0.05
